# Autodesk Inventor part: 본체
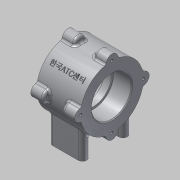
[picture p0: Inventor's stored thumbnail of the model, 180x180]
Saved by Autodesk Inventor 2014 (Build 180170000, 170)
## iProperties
Created: 2015-03
Part Number: 본체
Material: 알루미늄 6061
Document SubType Name: Modeling
Designer: MYHOME
Mass: 450.776 g
Surface Area: 332.745 cm^2
Volume: 166.338 cm^3
Density: 2.71 g/cm^3
Appearance: 알루미늄 - 평지
Author: MYHOME
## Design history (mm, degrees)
sketch "스케치2"
  geometry: C1 r 37 at (0, 0); 1 further point
  constraints: 1 centre point, 1 coincident
  dimensions: "d0" = 74 diameter of C1
extrude "돌출1" new body sketch "스케치2" stored distance "d1" = 52; taper "d2" = 0 deg
hole "구멍1" diameter "d5" = 42; stored, may be unused: countersink angle "d9" = 90 deg, drill point angle "d11" = 0 deg; dims "d3" = 10, "d4" = 10, "d6" = 6, "d7" = 47, "d8" = 22, "d10" = 30
sketch "스케치3"
  geometry: C1 r 37 at (0, 0) reference; C2 r 23.5 at (0, 0)
  constraints: 1 centre point, 1 coincident
  dimensions: "d12" = 47 diameter of C2
extrude "돌출2" cut sketch "스케치3" distance "d13" = 22; taper "d14" = 0 deg
sketch "스케치4"
  geometry: C1 r 23.5 at (0, 0) reference; C2 r 7 at (0, 37); C3 r 7 at (37, 0); C4 r 7 at (0, -37); C5 r 7 at (-37, 0); A1 r 37 centre (0, 0) between (0, 37) and (37, 0) reference
  constraints: 4 centre point, 4 point on circle, 2 horizontal alignment, 2 vertical alignment
  dimensions: "d16" = 7 radius of C2; "d17" = 7 radius of C3; "d18" = 7 radius of C4; "d19" = 7 radius of C5
extrude "돌출3" join sketch "스케치4" distance "d20" = 15; taper "d21" = 0 deg
fillet "모깎기1" dims "d22" = 3
fillet "모깎기2" dims "d23" = 3
chamfer "모따기1" distance "d24" = 1; stored, may be unused: second distance "d25" = 2, angle "d26" = 45 deg
fillet "모깎기3" dims "d27" = 0.3
sketch "스케치5"
  geometry: A1 r 7 centre (0, -37) between (-6.889, -38.239) and (6.889, -38.239) reference; A2 r 7 centre (37, 0) between (38.239, -6.889) and (38.239, 6.889) reference; A3 r 7 centre (0, 37) between (6.889, 38.239) and (-6.889, 38.239) reference; A4 r 7 centre (-37, 0) between (-38.239, 6.889) and (-38.239, -6.889) reference
hole "구멍2" sketch "스케치5" at (0, 37), (37, 0), (0, -37), (-37, 0) diameter "d29" = 3.242; stored, may be unused: countersink angle "d33" = 90 deg, drill point angle "d35" = 118 deg; dims "d30" = 8, "d31" = 47, "d32" = 22, "d34" = 11
chamfer "모따기2" distance "d36" = 1; stored, may be unused: second distance "d37" = 2, angle "d38" = 45 deg
node "작업 평면1"
sketch "스케치8"
  geometry: L1 (15, -24)-(-15, -24); L2 (15, -19)-(-15, -19); L3 (-15, -29)-(15, -29); L4 (15, 24)-(-15, 24); L5 (15, 29)-(-15, 29); L6 (-15, 19)-(15, 19); A1 r 5 centre (15, -24) between (15, -29) and (15, -19); A2 r 5 centre (-15, -24) between (-15, -19) and (-15, -29); A3 r 5 centre (15, 24) between (15, 19) and (15, 29); A4 r 5 centre (-15, 24) between (-15, 29) and (-15, 19); 3 further points
  constraints: 16 end point, 8 point on circle, 8 tangent, 4 centre point, 3 parallel, 2 midpoint, 2 vertical alignment, 1 horizontal
  dimensions: "d40" = 5 radius of A2; "d41" = 5 radius of A4; "d42" = 48 distance of point (0, 24) point (0, -24); "d43" = 40 dimension on A4 A3; "d44" = 40 dimension on A1 A2; "d45" = 24 distance of point (0, -24) point (0, 0)
extrude "돌출4" join sketch "스케치8" stored distance "d46" = 15; taper "d47" = 0 deg
sketch "스케치9"
  geometry: L1 (0, 0)-(-26.163, 26.163); L2 (0, 0)-(-37, 0); C1 r 1.621 at (-37, 0) reference; C2 r 1.621 at (37, 0) reference; C3 r 1.621 at (0, -37) reference; C4 r 1.621 at (0, 37) reference; C5 r 24.5 at (0, 0) reference; C6 r 24.5 at (0, 0) reference; A1 r 37 centre (0, 0) between (-9.104, 35.863) and (-35.863, 9.104) reference; A2 r 3 centre (-38.77, 9.842) between (-38.239, 6.889) and (-35.863, 9.104) reference; A3 r 7 centre (-37, 0) between (-38.239, 6.889) and (-38.239, -6.889) reference; A4 r 3 centre (-38.77, -9.842) between (-35.863, -9.104) and (-38.239, -6.889) reference; A5 r 37 centre (0, 0) between (-35.863, -9.104) and (-9.104, -35.863) reference; A6 r 3 centre (-9.842, -38.77) between (-6.889, -38.239) and (-9.104, -35.863) reference; A7 r 7 centre (0, -37) between (-6.889, -38.239) and (6.889, -38.239) reference; A8 r 3 centre (9.842, -38.77) between (9.104, -35.863) and (6.889, -38.239) reference; A9 r 37 centre (0, 0) between (9.104, -35.863) and (35.863, -9.104) reference; A10 r 3 centre (38.77, -9.842) between (38.239, -6.889) and (35.863, -9.104) reference; A11 r 7 centre (37, 0) between (38.239, -6.889) and (38.239, 6.889) reference; A12 r 3 centre (38.77, 9.842) between (35.863, 9.104) and (38.239, 6.889) reference; A13 r 37 centre (0, 0) between (35.863, 9.104) and (9.104, 35.863) reference; A14 r 3 centre (9.842, 38.77) between (6.889, 38.239) and (9.104, 35.863) reference; A15 r 7 centre (0, 37) between (6.889, 38.239) and (-6.889, 38.239) reference; A16 r 3 centre (-9.842, 38.77) between (-9.104, 35.863) and (-6.889, 38.239) reference; 2 further points
  constraints: 4 end point, 1 coincident, 1 horizontal, 1 point on circle
  dimensions: "d48" = 45 deg angle of L1 L2
  node "투영된 루프1"
node "작업 평면2"
sketch "스케치10"
  geometry: 2 further points
  constraints: 1 coincident, 1 other
feature "엠보싱1" sketch "스케치10" dims "d19" = 7, "d49" = 0.5, "d50" = 0
sketch "스케치11"
  geometry: A1 r 5 centre (-15, -24) between (-15, -19) and (-15, -29) reference; A2 r 5 centre (15, -24) between (15, -29) and (15, -19) reference; A3 r 5 centre (-15, 24) between (-15, 29) and (-15, 19) reference; A4 r 5 centre (15, 24) between (15, 19) and (15, 29) reference; 1 further point
hole "구멍3" sketch "스케치11" at (-15, -24), (15, -24), (15, 24), (-15, 24) diameter "d51" = 4.134; stored, may be unused: countersink angle "d55" = 90 deg, drill point angle "d57" = 118 deg; dims "d52" = 6, "d53" = 47, "d54" = 22, "d56" = 8
fillet "모깎기4" dims "d58" = 3
node "솔리드1"
mirror "대칭1"
other parameters: "d39" = -56
